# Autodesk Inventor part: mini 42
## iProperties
Created: 2026-08
Part Number: mini 42
Document SubType Name: Modeling
Designer: Tomasz Łysek
Density: 1 g/cm^3
Author: Tomasz Łysek
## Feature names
1. Wyciągnięcie proste1 [Extrusion]
2. Faza1 [Chamfer]
